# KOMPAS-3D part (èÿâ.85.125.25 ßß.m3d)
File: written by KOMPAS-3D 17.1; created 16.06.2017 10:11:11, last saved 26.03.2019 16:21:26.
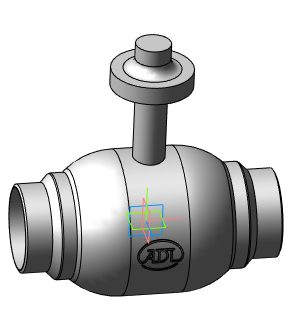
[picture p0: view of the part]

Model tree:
1. Операция без истории:2  (labels: Сталь 20  ГОСТ 1050-88)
